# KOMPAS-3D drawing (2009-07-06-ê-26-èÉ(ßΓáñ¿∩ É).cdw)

Views: Разрез 1-1. Разрез 2-2. Разрез 3-3., Разрез 4-4. Разрез 5-5. Разрез 6-6. Разрез 7-7., Разрез 8-8. Разрез 10-10., Разрез 9-9. Разрез 11-11. Разрез 12-12. Разрез 13-13., Разрез 1*-1*, Вид 1, Вид 2, Вид 3, Разрез 4-4. Разрез 5-5., Разрез 6-6. Разрез 7-7., Разрез 9-9. Разрез 11-11., Разрез 12-12. Разрез 13-13.
Referenced files in C:\Program Files\ASCON\KOMPAS-3D V10\Sys\: GRAPHIC.LHS
Referenced files: 2009-07-06-И-26-КР.cdw, 2009-07-06-И-26-КР511.cdw
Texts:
  Текст на чертеже
  Размерные надписи
  Шероховатость
  Линия-выноска #1
  Линия-выноска #2
  Линия-выноска #3
  Отклонения формы и база
  Заголовок таблицы
  Ячейка таблицы
  Стрелка вида
  Обозначение изменения
  Фигурная скобка
  Номер узла
  Марка координационной оси
  VRCB
  Выносная надпись
  Обозначение узла
  Марка/позиционное обозначение с линией-выноской
  Марка/позиционное обозначение на линии
  Марка/позиционное обозначение без линии-выноски
  Материал-Предприятие
  Лит-Масса-Масштаб
  FR4
  Лист
  Общие данные.
  Схема расположения монолитных железобетонных конструкций.
  Схема расположения существующих конструкций.
  Схема расположения монолитных железобетонных фундаментных плит.
  Разрезы а-а, б-б, в-в, г-г, д-д, е-е, ж-ж, и-и, к-к, л-л, м-м, н-н, п-п,
  Общие указания
  Рабочая документация марки КР разработана на основании следующих документов:
  - задание на проектирование (приложение №1 к договору №2009/07-06-И);
  - визуальное обследование конструкций подпорных стен, обмерные чертежи и рекомендации
  выполненные ЗАО Институт "ПИРС" в 2009-2010 гг на основании договора №2009/07-06, шифр
  - топографический план набережной, утвержденный заказчиком от 31.03.10 г.;
  - отчёт об инженерно-геологических изысканиях на объекте "Реконструкция набережной р. Кама в
  г. Перми" (II этап), выполненный ЗАО Верхнекам ТИСИз в 2010 г на основании договора №726.
  Рабочая документация разработана для района со следующими характеристиками:
  - нормативный скоростной напор ветра - 30 кг/м 2  в соответствии со СНиП 2.01.07-85;
  - расчетная снеговая нагрузка - 320 кг/м 2  в соответствии со СНиП 2.01.07-85;
  - расчетная температура наиболее холодной пятидневки (с коэффициентом обеспеченности 0,92)
  минус 35 С в соответствии со СНиП 2.01.01-82.
  Symbol type A
  Производство монолитных железобетонных конструкции выполнять в соответствии с требованиями
  СНиП 3.03.01-87 "Несущие и ограждающие конструкции".
  Производство земляных работ выполнять в соответствии со СНиП 3.02.01-87 "Земляные
  сооружения,  основания и фундаменты".
  При выполнении работ соблюдать требования по технике безопасности СНиП 12-04-02 и
  СНиП 12-03-01.
  Конструктивная характеристика
  лестницы-спуска с Комсомольского проспекта.
  Фундаменты подпорных стен - монолитные железобетонные на естественном основании
  толщиной 300, 400 мм с подготовкой из щебня фр. 20-40 мм толщиной 100 мм и прокладкой
  одного слоя из гидроизоляционного материала Биполь ХПП 3,0.
  Подпорные стены - монолитные железобетонные толщиной 300 и 400 мм. Подпорные стены
  запроектированы из бетона класса В20 W6 F300 и арматуры периодического профиля класса АIII
  диаметром 10, 16, 20 и 25 мм.
  Лестничные марши - монолитные железобетонные с жёстким защемлением в теле подпорных
  стен из бетона класса В20 W6 F300 и арматуры периодического профиля класса АIII  10 мм.
  Лестничные площадки - монолитные железобетонные с жёстким защемлением в теле подпорных
  Вдоль осей "2", "3", "5", "6" между осями "Б", "В" предусмотрены деформационные швы с
  заполнением материалом Пеноплэкс 35.
  Ведомость ссылочных и прилагаемых документов
  Ссылочные документы
  Прилагаемые документы
  Спецификация к схеме расположения монолитных железобетонных
  конструкций
  Спецификация на 1 элемент
  Ведомость спецификаций
  Ведомость видов работ, для которых необходимо составление актов
  освидетельствования скрытых работ.
  Бетонные и железобетонные конструкции монолитные
  Приемка смонтированной и установленной опалубки, контроль соответствия
  Приёмка подготовки основания и устройства гидроизоляционного слоя.
  СНиП 3.02.01-87
  положения разбивочным осям.
  Освидетельствование арматуры рабочим чертежам.
  Отбор контрольных образцов бетона.
  Проверка и приемка всех конструкций и их элементов, закрываемых в процессе
  последующего бетонирования.
  Приемка качества законченных бетонных и ж/б конструкций.
  Проверка устройства деформационных швов.
  Рабочие чертежи разработаны в соответствии с градостроительным планом
  земельного участка, заданием на проектирование, градостроительным регламентом,
  техническими регламентами, в том числе устанавливающие требования безопасной
  эксплуатации здания, сооружения, безопасного использования прилегающих к ним
  территорий, и с соблюдением технических условий.
  Главный инженер проекта                                   И.С. Богданова
  Ведомость рабочих чертежей основного комплекта
  Примечания
  Общие указания смотри на листе 1.
  За отм. 0.000 принят уровень основания лестницы, соответствующий абсолютной
  отметке 103.42 в Балтийской системе высот.
  Объемы работ по демонтажу конструкций:
  демонтаж железобетонных лестничных маршей - 55,4 м 3 ;
  демонтаж железобетонных лестничных площадок - 24,2 м 3 ;
  демонтаж бетонных подпорных стенок - 305,5 м 3 .
  Размеры и высотные отметки существующей лестницы-спуска с Комсомольского проспекта
  приняты, согласно материалов обследования, выполненных в 2010 г.
  ПС1
  ПС2б
  ПС2а
  ПС3а
  ПС4а
  ПС5
  ПС6
  ПС7
  ПС8
  ПС9а
  ПС10а
  ПС11а
  ПС12
  ПС14
  ПС13
  ПС16а
  ПС15
  ПС-1
  ПС-2
  ПС-3б
  ПС-3а
  ПС-4б
  ПС-4а
  ПС-5
  ПС-6
  ПС-7
  ПС-9б
  ПС-9а
  ПС-10а
  ПС-10б
  ПС-11б
  ПС-11а
  ПС-12
  ПС-13
  ПС-16а
  ПС-16б
  ПС-15
  ЛМ-1б
  ПЛм-1
  ЛМ-1а
  ЛМ-2
  ПЛм-2
  ПЛм-3
  ПЛм-4
  ЛМ-3
  ЛМ-4
  ЛМ-5
  ПЛм-5
  ПЛм-6
  ПЛм-7
  ЛМ-7
  ЛМ-6
  ур. з.
  ур.з
  Разрезы 1-1, 2-2, 3-3 смотри ни листе 5.
  Разрезы 4-4, 5-5, 6-6, 7-7 смотри на листе 6.
  Разрезы 8-8, 10-10 смотри на листе 7.
  Разрезы 9-9, 11-11, 12-12, 13-13 смотри на листе 8.
  Расход материалов на устройство 4-х деформационных швов - пеноплэкс 35 - 0,4 м 3  при толщине
  листов 40 мм.
  Схема расположения монолитных фундаментных плит.
  Основанием для фундаментных плит подпорных стен служит песок мелкий с расчётным
  сопротивлением не менее 2,0 кгс/см 2  и песчаник сильновыветрелый с расчётным
  сопротивлением не менее 3,89 кгс/см 2 .
  Геолого-литологический разрез на площадке лестницы-спуска с Комсомольского проспекта
  до глубины 5 м следующий (сверху-вниз):
  песок гравелистый коричневый средней степени водонасыщения - 0,2-2,1 м;
  песок мелкий коричневый средней плотности и средней степени водонасыщения - 2,1-3,5 м;
  песчаник коричневый, серовато-коричневый, среднезернистый на глинисто-карбонатном
  цементе, малопрочный, размягчаемый, сильновыветрелый - 3,5-5,0 м.
  При изысканиях грунтовые воды не встречены.
  Грунт основания фундаментных плит, лестничных маршей и лестничных площадок
  утрамбовать до коэффициента уплотнения 0,92.
  Под фундаментные плиты, лестничные марши и лестничные площадки выполнить подготовку
  из щебня фракции 20-40 мм толщиной 100 с прокладкой между щебнем и бетоном монолитных
  конструкций одного слоя гидроизоляции из гидроизоляционного материала Биполь ХПП 3,0.
  Обратную засыпку пазух котлованов выполнить местным непучинистым грунтом.
  Условные обозначения смотри на листе 3.
  Разрезы 1-1, 2-2, 3-3 замаркированы ни листах 3, 4.
  из щебня фракции 20-40 мм толщиной 100 мм с прокладкой между щебнем и бетоном
  монолитных конструкций одного слоя гидроизоляции из гидроизоляционного материала
  Биполь ХПП 3,0.
  Каркасы подпорных стен и сетки лестничных маршей и лестничных площадок выполнить из
  из отдельных стержней из арматуры класса АIII по ГОСТ 5781-82*. Соединения арматуры
  выполнить вязальной проволокой диаметром 1,2-1,5 мм по ГОСТ 3282-74 в шахматном порядке,
  а по краю элементов конструкции лестницы-спуска в каждом пересечении .
  Арматурные стержни по длине соединяются в холодный стык с нахлёстом величиной в 40
  диаметров соединяемых стержней, или при помощи ручной дуговой сварки (тип соединения
  С23-Рэ по ГОСТ 14098-91) с длиной шва 8 диаметров соединяемых стержней.
  Нижняя арматура укладывается на фиксаторы защитного слоя толщиной 40 мм. Защитный
  слой вертикальной арматуры подпорных стен - 40 мм.
  Разрезы 4-4, 5-5, 6-6, 7-7 замаркированы ни листах 3, 4.
  Разрезы 8-8, 10-10 замаркированы ни листах 3, 4.
  Разрезы 9-9, 11-11, 12-12, 13-13 замаркированы ни листах 3, 4.
  Разрезы а-а, б-б, в-в, г-г, д-д замаркированы ни листе 5.
  Разрезы е-е, ж-ж, и-и, к-к замаркированы ни листе 6.
  Разрезы л-л, н-н замаркированы ни листе 7.
  Разрезы м-м, п-п, р-р, с-с, т-т, у-у замаркированы ни листе 8.
  Расход арматуры на элементы смотри на листах 5, 6, 7, 8.
  Поз.
  Марка.
  Кол-во
  ед, кг
  Подпорная стена ПС-1
  ПС-8
  ПС-14
  Подпорная стена ПС-2
  Лестничный марш ЛМ-1а
  Монолитная лестничная площадка ПЛм-1
  Подпорная стена ПС-3а
  Подпорная стена ПС-3б
  Лестничный марш ЛМ-2
  Монолитная лестничная площадка ПЛм-2
  Подпорная стена ПС-4а
  Подпорная стена ПС-4б
  Подпорная стена ПС-5
  Подпорная стена ПС-6
  Лестничный марш ЛМ-3
  Монолитная лестничная площадка ПЛм-3
  Подпорная стена ПС-7
  Подпорная стена ПС-8
  Подпорная стена ПС-9а
  Подпорная стена ПС-9б
  Лестничный марш ЛМ-4
  Монолитная лестничная площадка ПЛм-4
  Подпорная стена ПС-10а
  Подпорная стена ПС-10б
  Лестничный марш ЛМ-5
  Монолитная лестничная площадка ПЛм-5
  Подпорная стена ПС-11а
  Подпорная стена ПС-11б
  Подпорная стена ПС-12
  Подпорная стена ПС-13
  Лестничный марш ЛМ-6
  Монолитная лестничная площадка ПЛм-6
  Подпорная стена ПС-14
  Подпорная стена ПС-15
  Подпорная стена ПС-16а
  Подпорная стена ПС-16б
  Лестничный марш ЛМ-7
  Монолитная лестничная площадка ПЛм-7
  Место шурфовки
  Спецификация к схеме расположения монолитных
  железобетонных конструкций.
  Пеноплэкс 35
  ПС-10
  переменный
  для перильного ограждения
  для маршей и площадок
  для фундаментных плит
  лест. марш
  лест. площадка
  Подготовка из щебня
  Гидроизоляция
  Биполь 1 слой
  Бетон В20 W6 F300
  шаг  200
  шаг 400
  шаг  400
  шаг  100
  ПС-11
  ПС-16
  Щебень фр. 20-40 мм
  Площадка лестничная монолитная ПЛм-1
  Материалы
  Бетон класса В20 W6 F300
  Биполь ХПП 3,0
  Лестничный марш ЛМ-1б
  Площадка лестничная монолитная ПЛм-2
  Площадка лестничная монолитная ПЛм-3
  Площадка лестничная монолитная ПЛм-4
  Площадка лестничная монолитная ПЛм-5
  Площадка лестничная монолитная ПЛм-6
  Площадка лестничная монолитная ПЛм-7
  ПС2
  Условные обозначения:
  Подпорная стена ПС
  монолитная железобетонная
  Монолитная фундаментная плита
  основание подпорной стенки
  ПЛм-...  - Лестничная площадка монолитная железобетонная;
  ЛМ-...  - Лестничный марш, монолитный железобетонный;
  Ведомость расхода стали на элемент, кг
  Марка
  элемента
  Изделия арматурные
  Арматура класса, кг
  Всего:
  АIII
  ГОСТ 5781-82*
  Итого:
  CONTINUOUS_RGB_0_0_0_THICK_0.3
  CONTINUOUS_RGB_0_0_0_THICK_0.18
  POLYLINE_STYLE_0.18_RGB_0_0_0
  CONTINUOUS_RGB_0_0_0_THICK_0.35
  CONTINUOUS_RGB_0_0_0_THICK_0.2
  CONTINUOUS_RGB_0_255_255_THICK_0.25
  CONTINUOUS_RGB_0_255_255_THICK_0.4
  CONTINUOUS_RGB_0_0_0_THICK_0.4
  CONTINUOUS_RGB_0_0_0_THICK_0.13
  CONTINUOUS_RGB_255_0_0_THICK_0.35
  CONTINUOUS_RGB_0_255_255_THICK_0.35
  CONTINUOUS_RGB_0_255_255_THICK_0.13
  GOST2.303 6_RGB_0_0_0_SC_0.1_THICK_0
  CONTINUOUS_RGB_255_255_0_THICK_0.25
  CONTINUOUS_RGB_0_255_255_THICK_0.3
  CONTINUOUS_RGB_0_0_0_THICK_0.25
  CONTINUOUS_RGB_255_255_0_THICK_0.3
  CONTINUOUS_RGB_255_255_0_THICK_0.35
  СТИЛИ-ЛИНИЙ-ПУНКТИРНАЯ-ЛИНИЯ_RGB_255_255_0_SC_0.08_THICK_0
  CONTINUOUS_RGB_255_0_0_THICK_0.25
  POLYLINE_STYLE_0.18_RGB_255_255_0
  CONTINUOUS_RGB_255_255_0_THICK_0.4
  POLYLINE_STYLE_0.18_RGB_255_0_0
  CONTINUOUS_RGB_0_0_0_THICK_0.09
  CONTINUOUS_RGB_192_192_192_THICK_0.13
  CONTINUOUS_RGB_0_0_0_THICK_0.15
  Штрихштриховая_RGB_0_0_0_SC_1_THICK_0.18
  С изломами_RGB_0_0_0_SC_1_THICK_0.18
  style from library
  Монтажный
  Заводской
  СПЛОШНАЯ_И_ШТРИХПУНКТИРНАЯ_ANSI
  СПЛОШНАЯ_И_ШТРИХПУНКТИРНАЯ_ANSI 1
  ГРУНТ_ANSI
  ГРУНТ_ANSI 3
  AR-CONC_ANSI
  AR-CONC_ANSI 12
  AR-CONC_ANSI 11
  AR-CONC_ANSI 10
  AR-CONC_ANSI 9
  AR-CONC_ANSI 8
  AR-CONC_ANSI 7
  AR-CONC_ANSI 6
  AR-CONC_ANSI 5
  AR-CONC_ANSI 4
  AR-CONC_ANSI 3
  AR-CONC_ANSI 2
  AR-CONC_ANSI 1
  AR-CONC_ANSI 0
  Стили документа
  Реконструкция существующей лестницы-
  спуска с Комсомольского проспекта
  Разраб.
  Пелянёв
  ЗАО Институт "ПИРС"
  Схема расположения
  существующих конструкций.
  Схема расположения монолитных
  железобетонных фундаментных плит
  Разрезы а-а, б-б, в-в, г-г, д-д, е-е,
  ГИП
  Гл. спец АР
  Захаров Е.Н.
Dimensions and other numbers on the sheet: 2009/07-06-И-26-КР; 1; 7; 3; 2; 4; 5; 6; 8; 9; 2009/07-06-И-ТО;; 5130; 6200; 4847; 5960; 4660; 6090; 1900; 4780; 3170; 320; 5830*; 3564; 4740; 1930; 4880; 700; 2920; 1460; 3070; 3000; 480; 1100; 260; 420; 4804; 2950; 650; 5440; 4340; 6600; 4520; 760; 5260; 3830; 2700; 9967; 9116; 8782; 8040; 8712; 8374; 8319; 5143; 623; 1483; 2960; 2900; 3540; 720; 319,4; 320,6; +103,60; +103,57; +123,01; +122,89; +105,81; +108,05; +110,29; +112,53; +114,61; +116,53; +118,45; +120,37; +121,69; +103,70; +104,03; +106,30; +108,50; +110,00; +113,00; +114,60; +115,50; +117,00; +118,00; +104,65; +105,35; +108,20; +110,30; +112,50; +114,30; +115,20; +116,86; +117,80; +120,35; +122,59; +113,60; +114,90; +115,94; +104,60; +104,90; +114,33; 115,33; 114,50; 113,90; 113,30; 118,33; 117,73; 117,13; 116,53; 115,93; 118,37; 120,27; 112,60; 111,90; 111,20; 114,48; 113,88; 113,28; 113,64; 112,63; 111,98; 111,33; 110,50; 109,80; 109,09; 108,34; 107,59; 106,84; 105,74; 104,61; 103,81; 102,37; 101,54; 103,11; 102,00; 10; 12; 11; 13; 3100; 610; 450; 750; 1950; 1200; 600; 1800; 2400; 1615; 2310; 1550; 1230; 2000; 960; 3900; 570; 1210; 385; 815; 12300; 48800; 6400; 8400; 11000; 6000; 28000; 2625; 1380; 5600; 2690; 9670; 3450; 620; 360; 5525; 345; 4760; 70; 2970; 2620; 690; 3040; 1565; 970; 380; 5220; 5680; 3720; 1300; 5340; 3770; 355; 1470; 4070; 3130; 3650; 9400; 5640; 300; 3495; 8755; 8940; 5580; 1120; 1350; 1750; 4825; 3530; 3120; 1650; 2490; 7210; 2865; 3200; 9175; 1640; 3360; 2440; 2065; 2090; 440; 900; 0,000; +2,325; +4,580; +6,760; +8,930; +11,180; +13,210; +15,085; +19,360; +17,100; 12284; 4860; 3503; 12250; 6229; 6668; 48793,5; 2009/07-06-И-26-КР-5; 2009/07-06-И-26-КР-6; 2009/07-06-И-26-КР-7; 2009/07-06-И-26-КР-8; 350; 120; 40; 123,01; 121,69; 120,37; 122,89; 119,07; 115,94; 113,60; 110,53; 109,25; 105,81; 124,21; 4950; 18240; 170; 200; 11х120=; 1320; 10х350=; 3500; 2650; 1000; 10х120=; 9х350=; 3150; 430; 3850; 2640; 124,09; 121,57; 470; 2250; 12270; 118,45; 119,65; 1310; 15х120=; 15х350=; 5250; 1450; 14х350=; 4900; 117,85; 5190; 30; 115,81; 114,61; 16х120=; 1920; 1035; 4820; 1150; 5180; 3940; 3937,5; 11475; 3550; 1090; 2983; 114,60; 112,53; 16х130=; 2080; 1250; 3420; 870,6; 1170; 1780; 3350; 113,73; 5630; 1880; 90; 390; 2130; 920; 110,29; 111,49; 108,05; 5200; 1610; 1570; 400; 103,57; 104,90; 3270; 107,01; 2115; 3725; 6150; 75; 5290; 6760; 6700; 16х140=; 2240; 3280; 850; 106,70; 106,53; 107,13; 3800; 6900; 1600; 1500; 270; 2100; 330; 3680; 6х140=; 3375; 8060; 2989,9; 1789,9; 1650,1; 1-1; 2-2; 3-3; 4-4; 7-7; 6-6; 5-5; 8-8; 10-10; 9-9; 12-12; 13-13; 11-11; 28140; 35; 660; 119,94; 120,84; 118,00; 115,50; 115,86; 114,16; 113,83; 110,00; 116,64; 113,00; 100; 105,39; 107,58; 106,36; 104,80; 104,96; 103,71; 103,78; 460; 730; 3,7; 7,0; 34,7; 3,5; 30,4; 37,2; 86,4; 8,6; 5,7; 27,0; 2,7; 5,5; 25,8; 2,6; 64,2; 0,617; 1,58; 2,47; 235,5 кг; 615,6 кг; 183,3 кг; 175,1 кг; 1643,0 кг; 3493,4 кг; 1667,3 кг; 1439,5 кг; 13,0; 14,3; 1,4; 7,5; 15,6; 73,2; 7,3; 3,9; 19,5; 2,0; 353,6 кг; 496,8 кг; 132,3кг; 1,1; 17,8; 1,8; 4,7; 11,0; 10,1; 120,8 кг; 368,0 кг; 477,7 кг; 218,0 кг; 7,2; 6,2; 0,6; 7,4; 9,2; 0,9; 17,5; 6,8; 0,8; 6,1; 9,0; 4,0; 17,9; 347,7 кг; 118,8 кг; 322,7 кг; 365,6 кг; 156,8 кг; 121,5 кг; 1,3; 12,8; 1,9; 18,6; 210,5 кг; 521,4 кг; 126,2 кг; 4,5; 10,0; 1,0; 14,2; 14,7; 1,5; 7,7; 16,4; 76,2; 7,6; 3,6; 17,6; 62,1; 71,1; 7,1; 3,85; 671,5 кг; 359,0 кг; 517,2 кг; 119,5 кг; 2264,2 кг; 2386,0 кг; 1582,0 кг; 5,1; 11,9; 1,2; 10,2; 76,2 кг; 411,3 кг; 483,0 кг; 237,9 кг; 8,7; 8,9; 5,8; 0,5; 9,1; 14,6; 16,9; 1,7; 5,6; 11,7; 276,5 кг; 428,5 кг; 692,1 кг; 262,2 кг; 4,1; 18,3; 20,2; 124,2 кг; 137,1 кг; 4,9; 24,3; 2,4; 164,9 кг; 1643,0; 1439,5; 183,3; 175,1; 235,5; 615,6; 353,6; 496,8; 132,3; 477,7; 218,0; 368,0; 347,7; 120,8; 118,8; 322,7; 156,8; 521,4; 210,5; 3493,4; 365,6; 1667,3; 6803,7; 522,4; 121,5; 126,2; 671,5; 359,0; 517,2; 119,5; 483,0; 237,9; 411,3; 1582,0; 124,2; 137,1; 276,5; 428,5; 262,2; 164,9; 2386,0; 2264,2; 487,5; 6232,2; 03.11; 2009/07-06-И-26-КР-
